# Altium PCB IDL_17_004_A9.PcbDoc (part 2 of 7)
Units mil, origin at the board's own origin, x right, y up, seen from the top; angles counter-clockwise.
Board outline 9493.25 x 7199.68 mil, 6 copper layers (Top Layer - SIG1, Layer 2 - GND1, Layer 3 - PWR1, Layer 4 - PWR2, Layer 5 - GND2, Bottom Layer - SIG2), stack 60.592 mil thick; 403 components, 274 nets, 1834 pads, 1849 vias.
Unrouted connection lines stored in the file: 1.
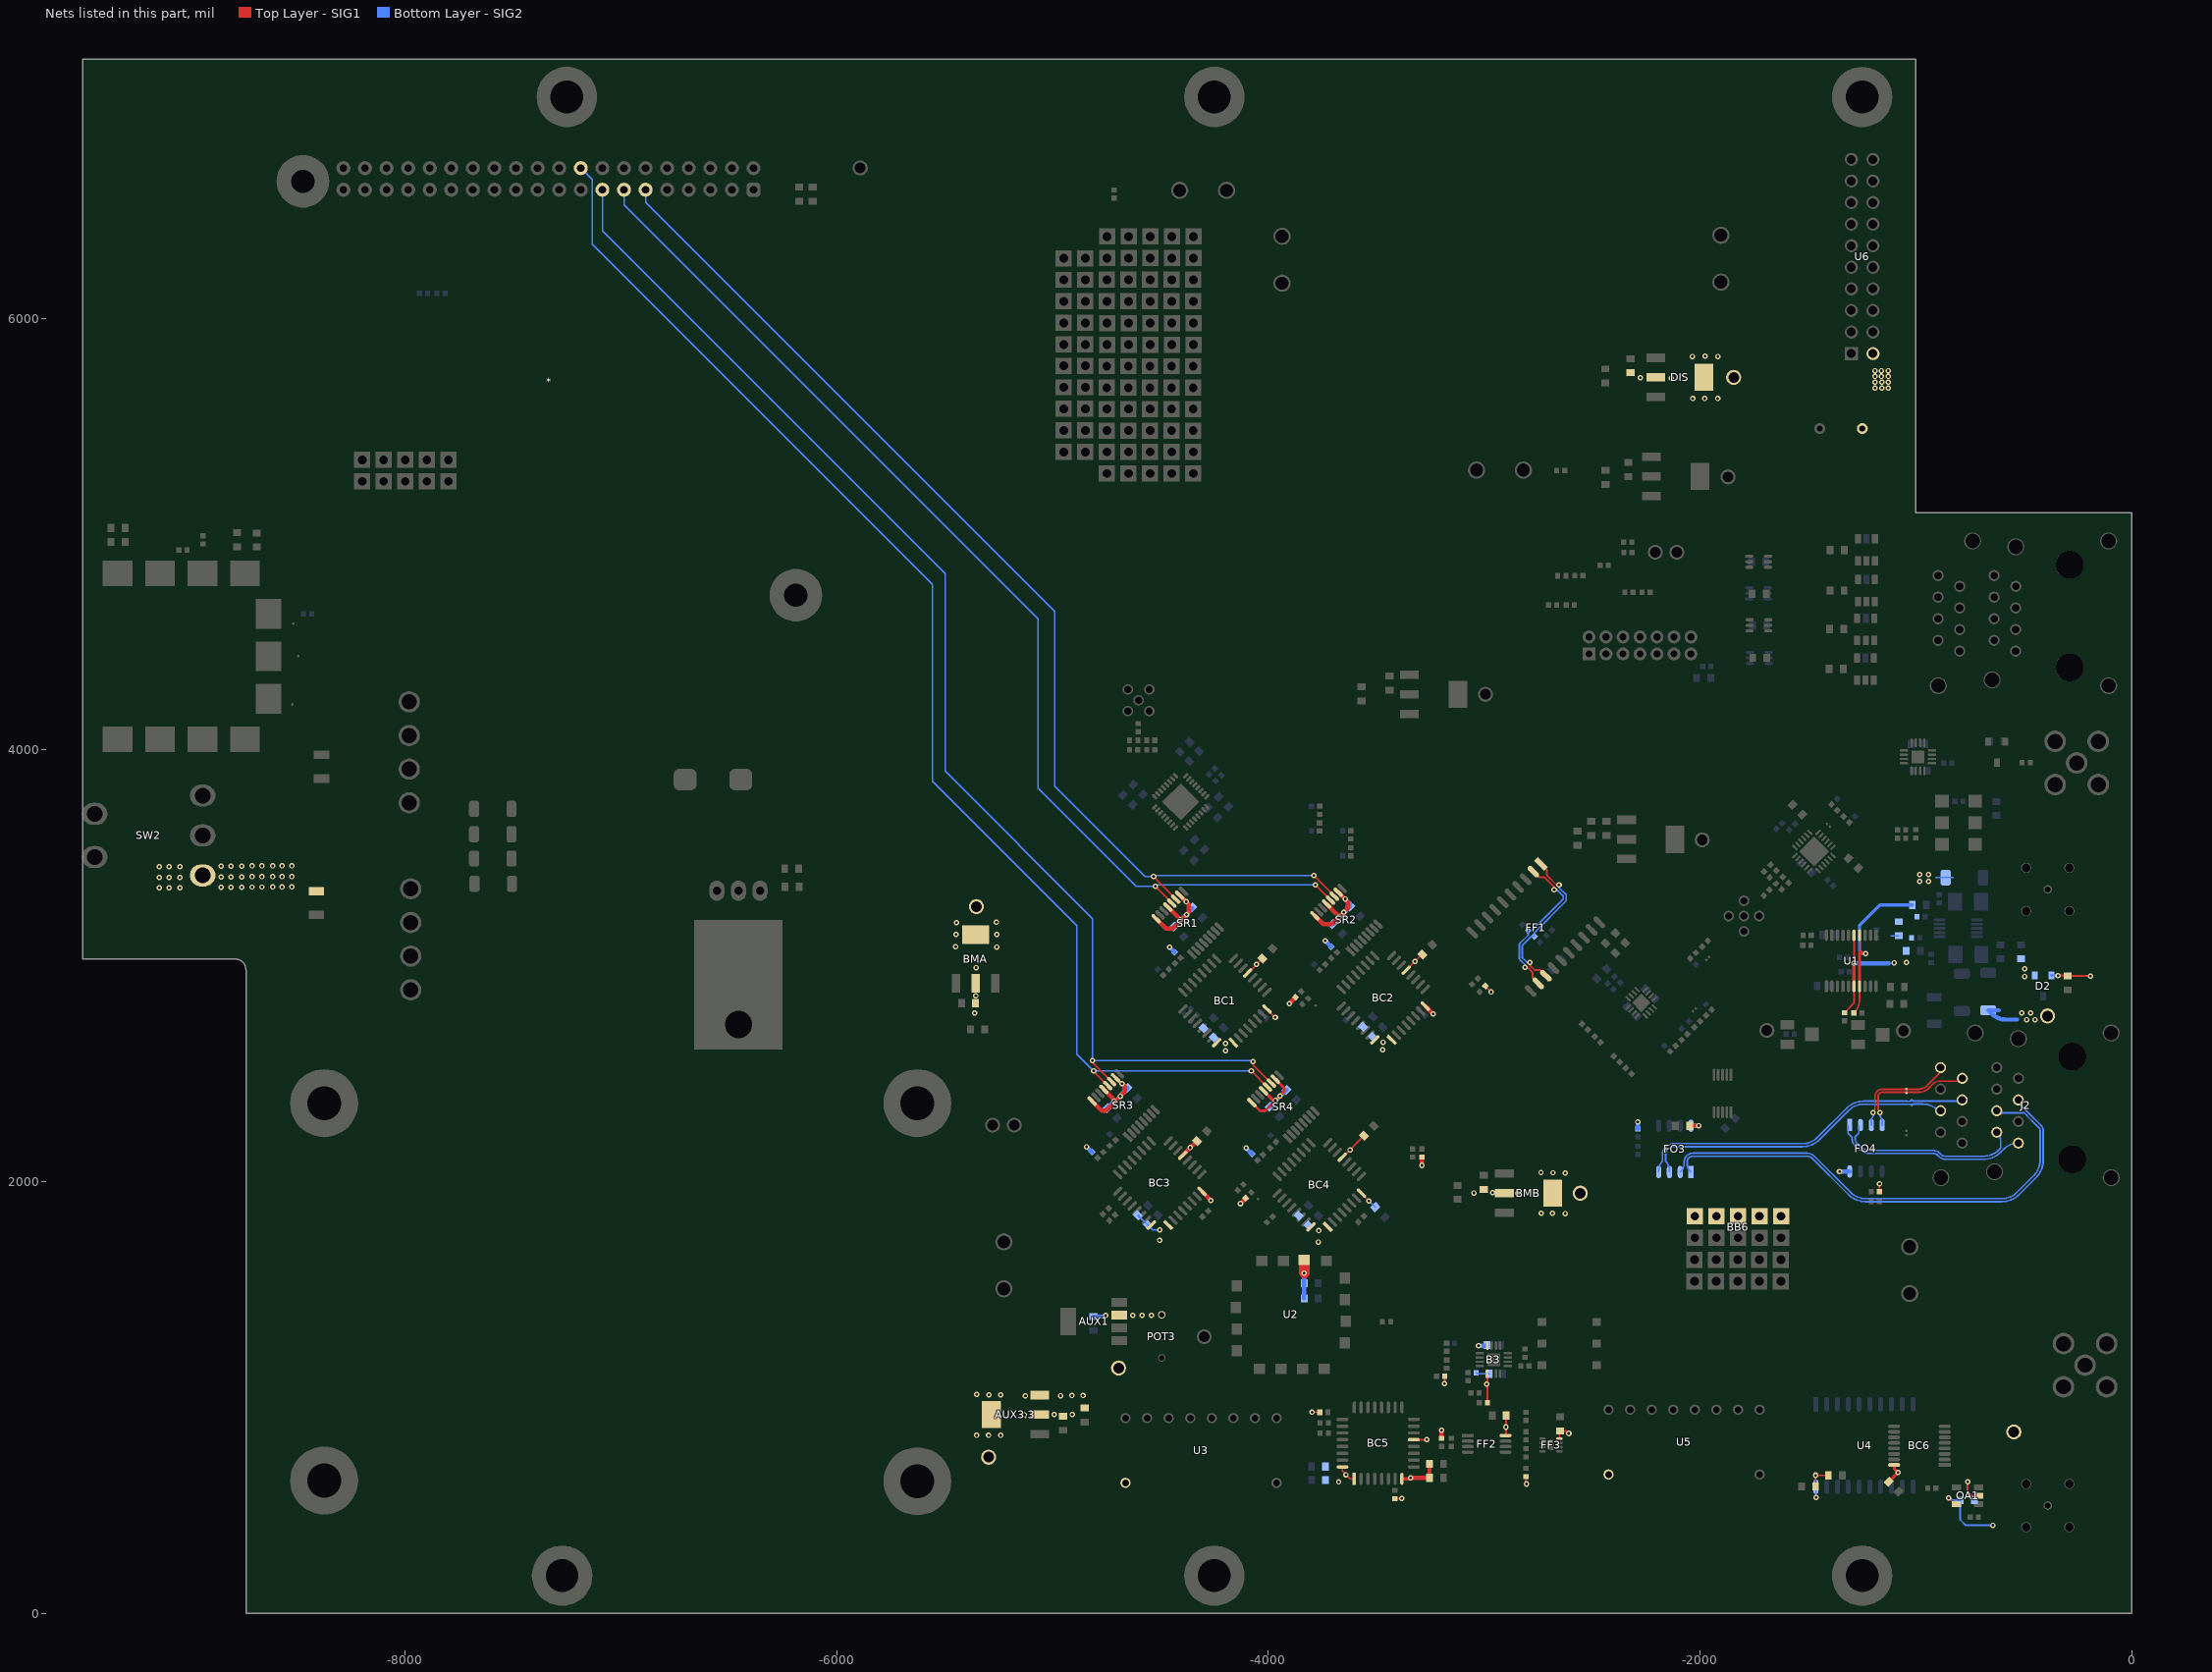
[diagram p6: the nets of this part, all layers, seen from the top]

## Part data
3V +5V -5V AUX3.3V RF3V RM3V RPI_5V TP20 TP21 TP24 TP25 TP30: library part TP, "TEST POINT PC MINI .040\"D BLACK"
*: "CONN HEADER FMAL 40PS.1\" DL GOLD"
AUX1: "IC REG LDO 5V 0.5A SOT223-5"
AUX3: "Linear Voltage Regulator IC Positive Fixed 1 Output 5V 5A TO-220-3"
AUX3.3 BMA BMB DIS JTAG RF RM: "IC REG LDO 3.3V 1A SOT223-3"
B1 B3: "IC CLK BUFFER 1:2 7.5GHZ 16LFCSP"
B2: "IC TRANSLATOR DUAL LVDS 10MSOP"
B4 B6 B7 B9 B10 B12: "IC HIGH DIFF LINE DRIVER SOT23-5"
B5 B8 B11: "IC BUFFER DUAL NON-INV SC706"
B13 B14: "IC DIFF LINE RECEIVER SOT-23-5"
BC1 BC2 BC3 BC4 BC5: "IC COUNTER 8BIT SYNC ECL 32LQFP"
BC6: "IC BINARY COUNTER 8BIT 16-TSSOP"
C1 C2 C3 C4 C5 C6 C8 C9 C11 C12 C13 C14 C15 C16 C17 C28 C34 C35 C36 C37 C38 C42 C43 C46 C47 C48 C49 C50 C51 C52 C53 C54 C55 C56 C59 C60 C61 C62 C63 C64 C65 C66 C67 C69 C70 C71 C72 C73 C74 C75 C76 C77 C78 C79 C80 C81 C86 C87 C102 C103 C104 C105 C106 C107 C108 C109 C110 C111 C112 C114 C115 C116 C118 C119 C400 C401 C402 C403: "CAP CER 1UF 25V X7R 0603"
C7 C10 C18 C19 C20 C21 C22 C23 C24 C25 C39 C40 C41 C44 C45 C57 C58 C68 C82 C83 C84 C85: "CAP CER 1000PF 50V X7R 0402"
C26 C27 C30 C31: "CAP CER 10000PF 50V X7R 0603"
C29 C32 C33 C89 C90 C91 C92 C93 C94 C95 C96 C97 C98 C99 C100 C101 C120: "CAP CER 0.1UF 50V X7R 0603"
C88: "CAP ALUM 470UF 20% 50V RADIAL"
C113: library part 1uF, "CAP CER 1UF 25V X7R 0603"
C117: library part CAPT7343_22U_25V, "Capacitor tantal smd 7343-31 25V 0.1Resr"
C121 C123 C124: "CAP CER 22UF 6.3V X5R 0603"
C122: "CAP CER 100PF 50V NP0 0603"
C125: "CAP CER 4.7PF 50V NP0 0603"
D1 D2: library part "HSMS-2822(seires diode)", "Surface Mount RF Schottky Barrier Diodes, Series Config."
D3 D4 D5 D6 D7 D8 D8: library part D-PMEG3050EP(DIODE), "Schottky diode 6A 30V 500ns 0.36Vf"
F0 F1: library part FUSE-8A6V, "Fuse 8A 6V SMDR"
FAN3 FAN4 J9 J10 J11 J18: "CONN HEADER 2POS 4.2MM VERT TIN"
FF1: "IC D-TYPE POS TRG DUAL 20SOIC"
FF2: "IC D-TYPE POS TRG SNGL 8MSOP"
FF3: "IC TRANSLATOR LVPECL-LVTTL 8-MLF"
FO1: "IC CLK BUFFER 1:8 4GHZ 32MLF"
FO2: "IC CLK BUFFER 1:4 3.5GHZ 16MLF"
FO3 FO4: "IC CLK BUFFER 1:2 650MHZ 8SOIC"
FO5: library part "ADP-2-9(PWR DIV)", "PWR SPL CMB / SM / RoHS5"
FP1: "DOUBLE NIM FRONT PANEL"
GPIO0 GPIO1 GPIO2 TP1 TP2 TP4 TP5 TP7 TP8 TP9 TP10 TP11 TP12 TP13 TP14 TP15 TP16 TP17: library part SMD_TP, "SURFACE MOUNT TEST POINT"
J1 J6: "CONN SMA JACK R/A 50 OHM PCB"
J2 J12: "CONN MOD JACK 8P8C R/A SHIELDED"
J3 J4: "CONN MMCX JACK STR 50 OHM PCB"
J5 J7: "CONN JACK R/A 50 OHM PCB"
J13 J14: "TWO PIN JUMPER"
J15 J17: "CONN HEADER 4POS 3.96MM VERT TIN"
L1 L2: "FIXED IND 10UH 520MA 854 MOHM"
M1: "IC BUFF/MUX SCHMITT-TRIG SC70-6"
MH1 MH2 MH3 MH4 MH5 MH6: "6-32 MOUNTING HOLE"
OA1: "IC OPAMP CFA 400MHZ TSOT23-5"
OSC1: "OSC VCO 127.21MHZ"
PLL1: "IC CLK GEN I2C BUS PROG 24QFN"
POT1: "TRIMMER 10K OHM 0.125W SMD"
POT2: "TRIMMER 2K OHM 0.125W SMD"
POT3: "TRIMMER 10K OHM 0.5W PC PIN"
PWR1: "IC REG BST SEPIC INV ADJ 10MSOP"
R1 R17 R107 R108 R110 R111 R112 R117 R120 R122 R123: "RES SMD 10K OHM 5% 1/16W 0402"
R2: "RES SMD 100 OHM 5% 1/16W 0402"
R3 R4 R5 R8 R18 R19 R20 R21 R23 R24 R27 R28 R29 R34 R35 R36 R40 R41 R42 R43 R44 R45 R46 R55 R56 R57 R58 R59 R60 R61 R62 R63 R64 R68 R72 R73 R74 R75 R76 R77 R78 R79 R80 R81 R85 R91 R94 R95 R96 R97 R99 R100 R102 R103 R104 RA1 RA2 RA3: "RES SMD 49.9 OHM 1% 1/16W 0402"
R6 R7 R38 R125: "RES SMD 1.62K OHM 1% 1/16W 0402"
R9 R10 R13 R14 R26 R31 R47 R48 R49 R50 R65 R66 R82 R83 R89 R90 R98: "RES SMD 127 OHM 1% 1/16W 0402"
R11 R12 R15 R16 R25 R30 R51 R52 R53 R54 R69 R70 R86 R87 R92 R93 R101: "RES SMD 82.5 OHM 1% 1/16W 0402"
R22: "RES SMD 49.9 OHM 1% 1/2W 1206"
R32 R67 R71 R84 R88 R105 R109: "RES SMD 1K OHM 5% 1/16W 0402"
R33 R39 R106: "RES SMD 4.02K OHM 1% 1/16W 0402"
R37: "RES SMD 665 OHM 1% 1/16W 0402"
R113 R114 R115 R116 R118 R119: "RES SMD 10 OHM 5% 1/16W 0402"
R121: "RES SMD 30.1K OHM 1% 1/16W 0402"
R124: "RES SMD 30.9K OHM 1% 1/10W 0402"
RAWPWR1: "AC-DC convertor"
SR1 SR2 SR3 SR4: "IC 8-BIT SHFT REG W/OUT 16-TSSOP"
TP3 TP6: library part "Test point", "TEST POINT PC MINI .040\"D BLACK"
U1: "IC COMPARATOR HS 20-TSSOP"
U2: "OSC VCO 490-540MHZ SMD .5X.5\""
U3 U5: "DIP SW 8POS EXTEND ACTUATOR 24V"
U4: "IC COMPARATOR MAGNITUDE 20SOIC"
U6: "DISPLAY FULL COLOR OLED 1.69\""
U7: "CONN HEADER 14POS 2MM GOLD DIP"

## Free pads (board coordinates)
  round 5 on Top Overlay: 1(-2748.44,6681.85) 1(-2748.44,6681.85) 1(-2748.14,6676.66) 1(-2748.14,6676.66) 1(-2743.81,6672.74) 1(-2743.81,6672.74) 1(-2741.97,6691.61) 1(-2741.97,6691.61) 1(-2739.48,6681.67) 1(-2739.48,6681.67) 1(-2735.29,6695.64) 1(-2735.29,6695.64) 1(-2730.63,6686.62) 1(-2730.63,6686.62) 1(-2729.9,6701.35) 1(-2729.9,6701.35) 1(-2729.9,6701.35) 1(-2729.9,6701.35) 1(-2727.63,6695.24) 1(-2727.63,6695.24) 1(-2695.1,6706.68) 1(-2695.1,6706.68) 1(-2693.19,6700.42) 1(-2693.19,6700.42) 1(-2689.65,6712.89) 1(-2689.65,6712.89) 1(-2687.32,6718.72) 1(-2687.32,6718.71) 1(-2687.32,6718.71) 1(-2687.32,6718.72) 1(-2679.84,6692.48) 1(-2679.84,6692.48) 1(-2676.68,6723.8) 1(-2676.68,6723.8) 1(-2674.12,6687.19) 1(-2674.12,6687.19) 1(-2666.47,6685.46) 1(-2666.47,6685.46) 1(-2666.44,6727.41) 1(-2666.44,6727.41) 1(-2658.56,6726.63) 1(-2658.56,6726.63) 1(-2657.46,6684.14) 1(-2657.46,6684.14) 1(-2649.41,6686.89) 1(-2649.41,6686.89) 1(-2649.08,6726.99) 1(-2649.08,6726.99) 1(-2642.41,6696.28) 1(-2642.41,6696.28) 1(-2641.92,6722.83) 1(-2641.92,6722.83) 1(-2641.66,6705.13) 1(-2641.66,6705.13) 1(-2637.83,6715.63) 1(-2637.83,6715.63) 1(-2518.23,6640.9) 1(-2518.23,6640.9) 1(-2517.85,6645.22) 1(-2517.85,6645.22) 1(-2511.85,6629) 1(-2511.85,6629) 1(-2510.84,6645.5) 1(-2510.84,6645.5) 1(-2504.94,6616.56) 1(-2504.94,6616.56) 1(-2502.47,6646.46) 1(-2502.47,6646.46) 1(-2501.16,6611.22) 1(-2501.16,6611.22) 1(-2496.15,6651.89) 1(-2496.14,6651.89) 1(-2496.14,6651.9) 1(-2496.14,6651.9) 1(-2494.88,6610.18) 1(-2494.88,6610.18) 1(-2489.89,6659.52) 1(-2489.89,6659.52) 1(-2488.9,6618.86) 1(-2488.9,6618.86) 1(-2486.92,6611.01) 1(-2486.92,6611.01) 1(-2486.65,6614.49) 1(-2486.65,6614.49) 1(-2486.34,6620.83) 1(-2486.34,6620.83) 1(-2486.15,6618.5) 1(-2486.15,6618.5) 1(-2485.29,6660.64) 1(-2485.29,6660.64) 1(-2483.78,6614.82) 1(-2483.78,6614.82) 1(-2483.34,6612.32) 1(-2483.34,6612.32) 1(-2483.16,6621.26) 1(-2483.16,6621.26) 1(-2481.75,6657.3) 1(-2481.75,6657.3) 1(-2478.72,6612.49) 1(-2478.72,6612.49) 1(-2473.9,6611.85) 1(-2473.9,6611.85) 1(-2473.34,6642.42) 1(-2473.34,6642.42) 1(-2470.26,6640.19) 1(-2470.26,6640.19) 1(-2470.2,6635.99) 1(-2470.2,6635.99) 1(-2470.04,6631.45) 1(-2470.04,6631.45) 1(-2469.15,6607.36) 1(-2469.15,6607.36) 1(-2466.63,6628.2) 1(-2466.63,6628.2) 1(-2463.6,6625.16) 1(-2463.6,6625.16) 1(-2461.93,6627.19) 1(-2461.93,6627.19) 1(-2460.26,6629.81) 1(-2460.26,6629.81) 1(-2457.92,6605.64) 1(-2457.92,6605.64) 1(-2457.25,6628.54) 1(-2457.25,6628.54) 1(-2455.46,6619.13) 1(-2455.46,6619.13) 1(-2448.15,6610.82) 1(-2448.15,6610.82) 1(-2406.23,6585.93) 1(-2406.23,6585.93) 1(-2405.99,6592.03) 1(-2405.99,6592.03) 1(-2401.49,6599.4) 1(-2401.49,6599.4) 1(-2400.12,6601.97) 1(-2400.12,6601.97) 1(-2398.91,6585.06) 1(-2398.91,6585.06) 1(-2395.52,6600.96) 1(-2395.52,6600.96) 1(-2382.46,6586.78) 1(-2382.46,6586.78) 1(-2378.01,6559.09) 1(-2378.01,6559.09) 1(-2377.62,6563.27) 1(-2377.62,6563.27) 1(-2373.5,6565.41) 1(-2373.5,6565.41) 1(-2372.89,6596.42) 1(-2372.89,6596.42) 1(-2371.26,6551.51) 1(-2371.26,6551.51) 1(-2368.04,6541.09) 1(-2368.04,6541.09) 1(-2367.82,6600.02) 1(-2367.82,6600.02) 1(-2362.77,6595) 1(-2362.77,6595.02) 1(-2362.77,6595.02) 1(-2362.77,6595) 1(-2358.6,6562.29) 1(-2358.6,6562.29) 1(-2357.09,6579.26) 1(-2357.09,6579.26) 1(-2357.03,6542.78) 1(-2357.03,6542.78) 1(-2349.38,6550.55) 1(-2349.38,6550.55) 1(-2343.52,6586.4) 1(-2343.52,6586.4) 1(-2341.89,6594.99) 1(-2341.89,6594.99) 1(-2339.54,6591.49) 1(-2339.54,6591.49) 1(-2336.76,6566.29) 1(-2336.76,6566.29) 1(-2335.73,6514.93) 1(-2335.73,6514.93) 1(-2334.21,6517.42) 1(-2334.21,6517.42) 1(-2333.18,6556.16) 1(-2333.18,6556.16) 1(-2332.75,6511.81) 1(-2332.75,6511.81) 1(-2331.75,6575.29) 1(-2331.75,6575.29) 1(-2331.75,6575.29) 1(-2331.75,6575.29) 1(-2327.55,6521.69) 1(-2327.55,6521.69) 1(-2327.55,6521.69) 1(-2327.55,6521.69) 1(-2325.97,6578.1) 1(-2325.97,6578.1) 1(-2322.16,6548.62) 1(-2322.16,6548.62) 1(-2322.02,6524.42) 1(-2322.02,6524.42) 1(-2320.58,6574.08) 1(-2320.58,6574.08) 1(-2318.77,6522.09) 1(-2318.77,6522.09) 1(-2317.87,6513.47) 1(-2317.87,6513.47) 1(-2315.18,6567.53) 1(-2315.18,6567.53) 1(-2310.18,6561.93) 1(-2310.18,6561.93) 1(-2310.12,6546.47) 1(-2310.12,6546.47) 1(-2308.33,6532.89) 1(-2308.33,6532.89) 1(-2304.08,6522.37) 1(-2304.08,6522.37) 1(-2298.5,6565.86) 1(-2298.5,6565.86) 1(-2287.47,6566.59) 1(-2287.47,6566.59) 1(-2283.09,6526.43) 1(-2283.09,6526.43) 1(-2280.72,6562.91) 1(-2280.72,6562.91) 1(-2273.78,6557.35) 1(-2273.78,6557.35) 1(-2270.28,6528.72) 1(-2270.28,6528.72) 1(-2260.7,6419.82) 1(-2260.7,6419.82) 1(-2259.26,6535.41) 1(-2259.26,6535.41) 1(-2258.16,6410.02) 1(-2258.16,6410.02) 1(-2257.51,6549.79) 1(-2257.51,6549.79) 1(-2256.48,6428.03) 1(-2256.48,6428.03) 1(-2254,6542.26) 1(-2254,6542.26) 1(-2252.07,6400.99) 1(-2252.07,6400.99) 1(-2250.2,6392.64) 1(-2250.2,6392.64) 1(-2248.59,6433.38) 1(-2248.59,6433.38) 1(-2245.82,6386.28) 1(-2245.82,6386.28) 1(-2244.16,6477.46) 1(-2244.16,6477.46) 1(-2243.85,6348.19) 1(-2243.85,6348.19) 1(-2243.19,6374.5) 1(-2243.19,6374.5) 1(-2242.34,6482.93) 1(-2242.34,6482.93) 1(-2242.18,6464.48) 1(-2242.18,6464.48) 1(-2241.58,6362.44) 1(-2241.58,6362.44) 1(-2241.22,6335.29) 1(-2241.22,6335.29) 1(-2239.7,6445.31) 1(-2239.7,6445.31) 1(-2236.14,6484.92) 1(-2236.14,6484.92) 1(-2236.14,6484.92) 1(-2236.13,6484.92) 1(-2235.68,6449.15) 1(-2235.68,6449.15) 1(-2235.58,6454.32) 1(-2235.58,6454.32) 1(-2231.62,6328.06) 1(-2231.62,6328.06) 1(-2219.92,6321.61) 1(-2219.92,6321.61) 1(-2219.08,6473.82) 1(-2219.08,6473.82) 1(-2217.09,6317.62) 1(-2217.09,6317.62) 1(-2214.08,6318.29) 1(-2214.08,6318.29) 1(-2207.3,6324.05) 1(-2207.3,6324.05) 1(-2201.88,6335.86) 1(-2201.88,6335.86) 1(-2196.72,6465.05) 1(-2196.72,6465.05) 1(-2193.76,6344.68) 1(-2193.76,6344.68) 1(-2168.19,6452.2) 1(-2168.19,6452.2) 1(-2167.56,6361.73) 1(-2167.56,6361.73) 1(-2156.67,6443.71) 1(-2156.67,6443.71) 1(-2155.62,6360.97) 1(-2155.62,6360.97) 1(-2147.95,6422.54) 1(-2147.95,6422.54) 1(-2147.91,6432.92) 1(-2147.91,6432.92) 1(-2146.76,6418.81) 1(-2146.76,6418.81) 1(-2145.31,6366.66) 1(-2145.31,6366.66) 1(-2143.87,6419.4) 1(-2143.87,6419.4) 1(-2138.12,6419.5) 1(-2138.12,6419.5) 1(-2135.88,6415.02) 1(-2135.88,6415.02) 1(-2131.64,6405.42) 1(-2131.64,6405.42) 1(-2128.9,6376.03) 1(-2128.9,6376.03) 1(-2121.94,6397.41) 1(-2121.94,6397.41) 1(-2116.64,6394.4) 1(-2116.64,6394.4) 1(-2115.92,6389.71) 1(-2115.92,6389.71)

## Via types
v1: diameter 25, hole 12, Top Layer - SIG1 to Bottom Layer - SIG2, tented both sides, 1502 vias
v2: diameter 25, hole 12, Top Layer - SIG1 to Bottom Layer - SIG2, 184 vias
v3: diameter 25.59, hole 11.81, Top Layer - SIG1 to Bottom Layer - SIG2, tented both sides, 163 vias

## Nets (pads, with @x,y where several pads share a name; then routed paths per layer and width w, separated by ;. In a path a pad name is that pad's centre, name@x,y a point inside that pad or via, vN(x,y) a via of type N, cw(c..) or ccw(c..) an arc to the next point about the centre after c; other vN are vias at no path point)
3V3AUX: AUX3.3.2 AUX3.3.4 AUX3.3V.1 B3.8 B3.13 BC5.1 BC5.8 BC5.13 BC5.32 BC6.16 C70.2 C72.2 C73.2 C74.1 C75.2 C76.1 C77.2 C78.1 C79.2 C80.1 C81.2 C82.2 C85.2 C118.2 FF2.8 FF3.8 R89.2 R90.2 R97.1 R98.2 R99.1 U3.9 U4.20 U5.9 | length 1317.5
  Top Layer - SIG1 w6: v1@-3797.23,931.98 R99.1@-3761.64,931.98 ; C118.2@-1465.12,589.06 v3(-1465.12,640.58)
  Top Layer - SIG1 w8: BC5.32@-3657.1,678.9 -3657.1,659.66 v1(-3640.51,643.08) -3621.22,623.79 BC5.1@-3601.98,623.79 ; R97.1@-3413.1,532.29 v1@-3384.05,532.29 ; v1@-3346.59,623.79 v1(-3341.79,628.59) ; BC5.13@-3326.39,804.89 v3(-3266.82,804.89) ; v3(-3183.9,1065.65) -3182.96,1066.59 C82.2@-3182.96,1099.98 ; B3.13@-2985.65,1110.91 -2985.65,1066.33 v3(-2988.73,1063.25) -2985.15,1059.68 R89.2@-2985.15,976.03 ; FF2.8@-2901.58,824.07 -2898.52,827.13 C81.2@-2898.52,917.38 ; C85.2@-2806.21,634.3 -2806.21,598.98 v3(-2805.21,599.98) ; FF3.8@-2651.84,810.19 -2651.84,843.11 C78.1@-2649.16,845.78 -2620.01,845.78 v3(-2608.21,833.98) ; v3(-1465.12,640.58) ccw(c-1463.87,641.84) -1463.87,640.06 C80.1@-1406.08,640.06
  Top Layer - SIG1 w14: BC5.32@-3669.18,678.9 BC5.32@-3657.1,678.9 ; BC5.8@-3381.51,623.79 v1@-3346.59,623.79 ; C79.2@-1125.97,609.58 -1101.6,633.94 -1101.6,635.4 v1(-1083.84,653.16) -1101.08,670.41 -1101.08,686.67 ccw(c-1102.86,686.67) BC6.16@-1101.6,687.93
  Top Layer - SIG1 w20: v1(-3341.79,628.59) C70.2@-3253.95,628.59 C73.2@-3253.95,693.33 ; v3(-3197.94,848.98) -3197.58,848.61 R98.2@-3197.58,811.96
  Bottom Layer - SIG2 w6: R90.2@-3037.71,1115.58 -3033.04,1110.91 C76.1@-2978.76,1110.91 ; v3(-2988.73,1063.25) v3@-2986.09,1060.62 ; v3(-1465.12,640.58) -1465.12,588.16 U4.20@-1463.79,586.82 v1(-1463.79,537.06)
  Bottom Layer - SIG2 w8: v3(-2988.73,1063.25) -2985.65,1066.33 -2985.65,1104.02 C76.1@-2978.76,1110.91
  Bottom Layer - SIG2 w20: v3@-3198.21,848.98 v3(-3197.94,848.98) ; v3@-3026.03,1240.16 v3(-3026.18,1240.31) -2991.23,1240.31 C75.2@-2987.97,1243.57
  other v1: -3382.94,532.38 -3674.46,609.14 -5351.01,825.24 -5296.01,825.24 -5239.91,825.24 -5130.01,920.24 -4993.01,921.24 -4909.01,921.24 -3797.33,932.07 -5239.91,1012.24 -5295.01,1013.24 -5352.01,1014.24
  other v3: -2900.96,863.73
5VAUX: AUX1.3 AUX3.3.3 C69.1 C71.1 C114.2 C116.2 POT3.1 TP25.1 U2.14 | length 237.1
  Top Layer - SIG1 w50: v1(-3834.29,1577.34) U2.14@-3834.29,1636.2
  Bottom Layer - SIG2 w20: C116.2@-4810.6,1375.54 -4759.12,1375.54 v1(-4753.6,1381.06) ; C69.1@-3834.29,1459.64 C114.2@-3834.29,1530.5 v1(-3834.29,1577.34) cw(c-3832.64,1577.34) v1@-3833.81,1578.5
  other v1: -5125.35,1007.55 -4963.12,1009 -4909.8,1009.52 -4859.11,1009.52 -4627.6,1380.96 -4584.44,1380.96 -4541.29,1380.96
+5V: +5V.1 C30.2 C31.2 C124.1 C125.2 D2.2 D8.1@-862.77,3408.33 OA1.5 R33.2 R124.1 U1.7 U1.14 | length 1479.1
  Top Layer - SIG1 w6: U1.7@-1261.76,2905.63 U1.7@-1261.39,2905.27 ; U1.14@-1261.76,3141.85 -1262,3141.61 -1262,3070.58 -1247.78,3056.37 v1(-1233.25,3056.37)
  Top Layer - SIG1 w8: R33.2@-1287.8,2781 ccw(c-1350.66,2843.87) -1261.76,2843.87 U1.7@-1261.76,2905.63 ; v3(-848.54,535.48) -824.39,511.33 ccw(c-811.68,524.04) OA1.5@-811.68,506.06 ; v3(-342.83,2955.39) -298.94,2955.39 C124.1@-297.22,2953.67 v1@-192.14,2953.67
  Top Layer - SIG1 w15: U1.7@-1261.76,2905.63 -1261.35,2906.04 -1261.35,3021.46 -1261.76,3021.87 -1261.76,3059.56 v1@-1237.13,3059.56
  Bottom Layer - SIG2 w6: -911,3409 -910.33,3408.33 D8.1@-862.77,3408.33 -827.34,3408.33
  Bottom Layer - SIG2 w8: v3(-848.54,535.48) cw(c-846.61,537.42) -849.35,537.42 ccw(c-820.4,566.36) -820.4,525.43 C31.2@-795.46,525.43 -795.46,434.08 -769.96,408.58 v1(-643.71,408.58) ; D2.2@-371.63,2955.46 -342.89,2955.46 v3(-342.83,2955.39)
  Bottom Layer - SIG2 w13: -1262,3187 -1262,3070.58 -1247.78,3056.37 v1(-1233.25,3056.37)
  Bottom Layer - SIG2 w15: -1262,3187 -1166.65,3282.35 C125.2@-1017.3,3282.35 ; D2.2@-371.63,2955.46 cw(c-370.32,2954.15) D2.2@-370.32,2956
  other v1: -192.08,2952.89 -983.62,3391.14 -941.83,3391.14 -983.62,3423.17 -941.83,3423.17
-5V: -5V.1 C30.1 C31.1 C122.2 C123.2 D2.1 D3.2 OA1.2 R39.1 R121.2 U1.6 U1.15 | length 981.3
  Top Layer - SIG1 w6: v3(-760.66,609.6) -760.66,565.28 -740.81,545.43 OA1.2@-709.32,545.43
  Top Layer - SIG1 w8: R39.1@-1332,2782.9 -1287.35,2827.55 U1.6@-1287.35,2905.63
  Top Layer - SIG1 w10: v1(-1287.35,3010.69) U1.15@-1287.35,3141.85
  Top Layer - SIG1 w15: U1.6@-1287.35,2905.63 v1(-1287.35,3010.69)
  Bottom Layer - SIG2 w6: v1(-1287.35,3010.69) cw(c-1292.1,3005.94) v1@-1285.38,3005.94 ; -1118,3139 -1117.37,3139.63 C30.1@-1079.31,3139.63 ; v3(-760.66,609.6) -760.66,555.6 C31.1@-730.5,525.43
  Bottom Layer - SIG2 w20: v1(-1287.35,3010.69) -1126.55,3010.69 -1125.57,3011.68 ; -616.58,2794.16 D3.2@-665.92,2794.16 -652.05,2780.29 ccw(c-581.34,2851) -581.34,2751 -532,2751
  other v1: -488,2751 -448.67,2751 -510,2781 -469.33,2781 -497,2951 -497,2986 -1101.25,3014.83 -1044.25,3015.83
ACDC_PWR: F0.2 SW2.1
  other v1: -9138.37,3361.74 -9092.37,3361.74 -9042.37,3361.86 -8851.29,3364.41 -8805.29,3364.41 -8755.29,3364.53 -8708.42,3365.08 -8662.42,3365.08 -8612.42,3365.2 -8569.42,3365.2 -8523.42,3365.2 -9138.37,3409.62 -9092.37,3409.62 -9042.37,3409.74 -8851.29,3412.29 -8805.29,3412.29 -8755.29,3412.41 -8708.42,3412.96 -8662.42,3412.96 -8612.42,3413.08 -8569.42,3413.08 -8523.42,3413.08 -9138.37,3459.62 -9092.37,3459.62 -9042.37,3459.74 -8851.29,3462.29 -8805.29,3462.29 -8755.29,3462.41 -8708.42,3462.96 -8662.42,3462.96 -8612.42,3463.08 -8569.42,3463.08 -8523.42,3463.08
BMA1_N: FO3.2 J2.4 | length 2293.5
  Bottom Layer - SIG2 w8: FO3.2@-2092.5,2045.14 -2086.72,2050.92 ccw(c-2116.23,2080.42) -2074.5,2080.42 -2074.5,2091.42 cw(c-2033.87,2091.42) -2033.87,2132.06 -1504.76,2132.06 cw(c-1504.76,2084.35) -1471.03,2118.08 -1304.24,1951.29 ccw(c-1233.53,2022) -1233.53,1922 -602.42,1922 ccw(c-602.42,2022) -531.71,1951.29 -454.29,2028.71 ccw(c-525,2099.42) -425,2099.42 -425,2235 ccw(c-449.14,2235) -432.07,2252.07 -499.83,2319 ; J2.4@-626,2329 -616,2319 -499.83,2319 ; -486.01,2306.01 -499.83,2319
BMA1_P: FO3.1 J2.5 | length 2210.2
  Bottom Layer - SIG2 w8: FO3.1@-2042.5,2045.14 -2048.28,2050.92 cw(c-2018.78,2080.42) -2060.5,2080.42 -2060.5,2091.42 cw(c-2033.87,2091.42) -2033.87,2118.06 -1504.76,2118.06 cw(c-1504.76,2084.35) -1480.93,2108.18 -1314.14,1941.39 ccw(c-1233.53,2022) -1233.53,1908 -602.42,1908 ccw(c-602.42,2022) -521.81,1941.39 -444.39,2018.81 ccw(c-525,2099.42) -411,2099.42 -411,2235 ccw(c-449.14,2235) -422.17,2261.97 -476.1,2315.9 -525.67,2365.47 -526.01,2365.47 J2.5@-526.01,2369.01
BMA2_N: FO3.4 J2.12 TP13.1 | length 1578
  Bottom Layer - SIG2 w8: FO3.4@-2192.5,2045.14 -2192.5,2052.23 cw(c-2131.05,2052.23) -2174.5,2095.68 -2174.5,2127.7 cw(c-2129.77,2127.7) -2161.4,2159.32 cw(c-2120.12,2118.04) -2120.12,2176.42 -1527,2176.42 ccw(c-1527,2276.42) -1456.29,2205.71 -1322.27,2339.73 cw(c-1241.66,2259.12) -1241.66,2373.12 -1040.04,2373.12 -1039.93,2373 -1029.66,2373 ccw(c-1029.66,2386.66) TP13.1@-1020,2377 ccw(c-1011.55,2385.45) -1011.55,2373.5 -796.85,2373.5 cw(c-796.85,2358.16) J2.12@-786.01,2369.01
BMA2_P: FO3.3 J2.13 TP12.1 | length 1467
  Bottom Layer - SIG2 w8: FO3.3@-2142.5,2045.14 -2142.5,2052.23 ccw(c-2203.96,2052.23) -2160.5,2095.68 -2160.5,2107.17 -2160.5,2127.7 cw(c-2129.77,2127.7) -2151.5,2149.42 cw(c-2120.12,2118.04) -2120.12,2162.42 -1527,2162.42 ccw(c-1527,2276.42) -1446.39,2195.81 -1312.37,2329.83 cw(c-1241.66,2259.12) -1241.66,2359.12 -1045.84,2359.12 -1045.72,2359 -1027.24,2359 cw(c-1027.24,2348.76) TP12.1@-1020,2356 cw(c-1011.55,2347.55) -1011.55,2359.5 -967.92,2359.5 cw(c-967.92,2259.5) -897.21,2330.21 J2.13@-886,2319
BMA_3V3: BC1.1 BC1.8 BC1.13 BC1.32 BC2.1 BC2.8 BC2.13 BC2.32 BMA.2 BMA.4 C42.1 C43.2 C44.2 C45.2 C46.1 C47.2 C48.1 C49.2 C50.1 C51.2 C52.1 C53.2 C54.1 C109.2 FO3.8 R65.2 R66.2 R67.2 SR1.10 SR1.13 SR1.16 SR2.10 SR2.13 SR2.16 TP20.1 | length 1613.4
  Top Layer - SIG1 w6: BC1.13@-4095.42,2967.07 -4094.96,2967.07 C46.1@-4027.18,3034.84 ; BC1.8@-4006.33,2800.03 -3968.33,2762.03 v3(-3968.08,2762.03) ; -3684.42,3240.45 -3684.42,3239.53 v1(-3672.35,3227.45) ; R66.2@-2994.93,2906.31 v1@-2967.78,2879.17
  Top Layer - SIG1 w8: BC2.32@-3507.64,2656.72 BC2.32@-3507.03,2657.32 ; BC2.13@-3362.27,2980.25 -3320.75,3021.77 -3292.19,3050.33 cw(c-3286.22,3044.36) C51.2@-3286.22,3052.81
  Top Layer - SIG1 w20: SR1.16@-4519.83,3218.43 -4473.99,3172.59 -4444.26,3172.59 v1@-4406.69,3210.16 ; SR1.13@-4465.54,3272.72 v1(-4406.69,3213.86) v1@-4406.69,3210.16 ; SR1.10@-4411.26,3327 -4369.13,3284.87 -4369.13,3247.72 v1(-4379.23,3237.62) v1@-4406.69,3210.16 ; v3(-3903.35,2825.31) R65.2@-3874.36,2854.3 ; SR2.16@-3784.99,3232.45 -3746.05,3193.51 -3706.29,3193.51 v1(-3672.35,3227.45) v1(-3651.35,3248.45) -3632.45,3267.35 -3632.45,3297.06 SR2.10@-3676.42,3341.02 ; SR2.13@-3730.7,3286.73 -3684.42,3240.45 ; BC2.8@-3273.18,2813.22 -3237.42,2777.45 v1(-3237.35,2777.45) ; C48.1@-2045.04,2255 -2040.33,2259.71 v1(-2006.36,2259.71)
  Bottom Layer - SIG2 w20: v1@-4457.08,3085.58 C44.2@-4434.05,3062.56 ; C109.2@-4437.96,3181.2 C49.2@-4352.33,3266.83 ; v1(-3736.84,3116.12) -3708.58,3087.86 C45.2@-3708.58,3087.81 cw(c-3708.58,3092.44) C45.2@-3711.86,3089.17 ; C42.1@-3703.42,3193.51 -3672.35,3224.58 v1(-3672.35,3227.45) v1(-3651.35,3248.45) -3648.48,3248.45 C43.2@-3622.01,3274.92 -3622.01,3288.12 v1(-3644.35,3310.45) ; v1@-3238.35,2777.45 v1(-3237.35,2777.45) ; R67.2@-2288.99,2245.52 v1@-2288.99,2275.73 ; FO3.8@-2042.84,2260.05 FO3.8@-2042.5,2259.71 v1(-2006.36,2259.71)
  other v1: -2289.52,2276.25 -4198.87,2607.5 -3470.42,2610.74 -4198.9,2640.96 -3469.2,2646.2 -5359.95,2782.1 -5355,2862 -2967.78,2878.67 -5353.59,2992.11 -4055.02,3007 -3321.25,3020.77 -4457.08,3086.03 -5448.34,3088.27 -5258.13,3087.57 -5258.83,3144.84 -5447.63,3145.55 -5444.8,3200.7 -5259.54,3202.12 -4380.08,3297.03
BMA_RCLK: *.13 SR1.12 SR2.12 | length 5255.9
  Top Layer - SIG1 w6: *.13@-6988,6622.08 -6985,6625.08 *.13@-6985.26,6625.34 ; v3(-4524.57,3367.93) SR1.12@-4447.45,3290.81 ; v3(-3783.3,3375.52) SR2.12@-3712.61,3304.83
  Bottom Layer - SIG2 w6: *.13@-6985.12,6595.35 -6985.12,6524.12 -5068,4607 -5068,3824 -4611.93,3367.93 v3(-4524.57,3367.93) -4516.98,3375.52 v3(-3783.3,3375.52)
BMA_SRCLK: *.11 SR1.11 SR2.11 | length 5224.2
  Top Layer - SIG1 w6: *.11@-6885.26,6625.34 -6878,6618.08 *.11@-6884,6612.08 ; v3(-4531.57,3413.52) -4531.57,3411.12 SR1.11@-4429.35,3308.91 ; v3(-3788.57,3417.7) -3731.65,3360.77 cw(c-3732.86,3359.56) -3731.15,3359.56 SR2.11@-3694.51,3322.92
  Bottom Layer - SIG2 w6: *.11@-6885.12,6595.35 -6885.12,6537.12 -4990,4642 -4990,3832 -4571.52,3413.52 v3(-4531.57,3413.52) -4527.4,3417.7 v3(-3788.57,3417.7)
BMB1_N: FO4.2 J2.2 | length 862.3
  Bottom Layer - SIG2 w8: FO4.2@-1264.72,2257.4 -1264.72,2224.86 -1282.72,2206.86 -1282.72,2202 ccw(c-1248.23,2202) -1272.62,2177.62 -1260,2165 ccw(c-1211.72,2213.28) -1211.72,2145 -920.01,2145 cw(c-920.01,2103.35) -890.56,2132.8 -885.84,2128.07 ccw(c-861.32,2152.59) -861.32,2117.92 -688.02,2117.92 ccw(c-688.02,2217.92) -617.31,2147.21 -607.56,2156.96 -607.56,2184.48 ccw(c-670.52,2184.48) J2.2@-626,2229
BMB1_P: FO4.1 J2.1 | length 899.1
  Bottom Layer - SIG2 w8: FO4.1@-1314.72,2257.4 -1314.72,2224.86 -1296.72,2206.86 -1296.72,2202 ccw(c-1248.23,2202) -1282.51,2167.72 -1269.9,2155.1 ccw(c-1211.72,2213.28) -1211.72,2131 -920.01,2131 cw(c-920.01,2103.35) -900.46,2122.9 -895.74,2118.18 ccw(c-861.32,2152.59) -861.32,2103.92 -688.02,2103.92 ccw(c-688.02,2217.92) -607.41,2137.31 -593.79,2150.93 ; -593.79,2150.93 cw(c-526.01,2083.14) J2.1@-526.01,2179.01
BMB2_N: FO4.4 J2.10 TP16.1 | length 556.4
  Top Layer - SIG1 w8: v3(-1166.92,2321) cw(c-1145.69,2342.23) -1175.72,2342.23 -1175.72,2396 cw(c-1157.72,2396) -1157.72,2414 TP16.1@-1044.77,2414 ; TP16.1@-1044.68,2412.2 cw(c-1040.34,2407.85) -1040.34,2414 -991,2414 ccw(c-991,2488.36) -938.42,2435.78 -921.07,2453.13 cw(c-890,2422.06) -890,2466 -792.87,2466 ccw(c-792.87,2476.26) J2.10@-785.61,2469.01
  Bottom Layer - SIG2 w8: v3(-1166.92,2321) -1166.92,2304.15 cw(c-1189.14,2281.93) -1157.72,2281.93 FO4.4@-1157.72,2262.4
BMB2_P: FO4.3 J2.9 TP15.1 | length 497.6
  Top Layer - SIG1 w8: v3(-1198.51,2321) ccw(c-1219.74,2342.23) -1189.72,2342.23 -1189.72,2396 cw(c-1157.72,2396) -1157.72,2428 TP15.1@-1048.77,2428 ; TP15.1@-1045.06,2429.9 ccw(c-1040.46,2434.5) -1040.46,2428 -991,2428 ccw(c-991,2488.36) -948.32,2445.68 -893.78,2500.22 ccw(c-912.56,2519) J2.9@-886,2519
  Bottom Layer - SIG2 w8: FO4.3@-1207.72,2262.4 -1207.72,2281.93 cw(c-1176.29,2281.93) -1198.51,2304.15 v3(-1198.51,2321)
BMB_3V3: BB6.1 BB6.2 BB6.3 BB6.4 BB6.5 BC3.1 BC3.8 BC3.13 BC3.32 BC4.1 BC4.8 BC4.13 BC4.32 BMB.2 BMB.4 C55.1 C56.2 C57.2 C58.2 C59.1 C60.2 C61.1 C62.2 C63.1 C64.2 C65.1 C66.2 C67.1 C110.2 FO4.8 R82.2 R83.1 R84.2 SR3.10 SR3.13 SR3.16 SR4.10 SR4.13 SR4.16 TP21.1 | length 1743.7
  Top Layer - SIG1 w6: BC4.13@-3658.36,2113.87 -3656.13,2113.87 C66.2@-3556.97,2213.03
  Top Layer - SIG1 w8: BC3.32@-4541.99,1799.43 BC3.32@-4536.81,1799.43 ; BC4.8@-3569.28,1946.84 -3569.28,1946.58 v1(-3533.94,1911.23) ; R84.2@-1169.8,1954.43 -1169.8,1990.09 v1(-1168.71,1990.09)
  Top Layer - SIG1 w13: SR3.10@-4708.23,2481.99 -4707.19,2481.99 -4707.19,2479.92 v1@-4681.4,2454.13
  Top Layer - SIG1 w14: SR4.16@-4076.84,2366.7 -4038.27,2328.14 -4015.83,2328.14 -3926.49,2417.48 -3926.49,2433.5 SR4.10@-3968.26,2475.28 ; SR4.13@-4022.55,2420.99 -3980.4,2378.84
  Top Layer - SIG1 w20: SR3.16@-4816.8,2373.42 -4779.52,2336.14 ccw(c-4762.09,2353.57) -4762.09,2328.92 ; SR3.13@-4762.51,2427.7 -4717.6,2382.79 v1@-4717.6,2364.56 ; -4759.56,2327.87 cw(c-4759.56,2331.44) -4762.08,2328.91 ; v1@-4681.4,2454.13 v1(-4678.23,2454.13) -4664.45,2440.35 -4664.45,2417.71 v1@-4717.6,2364.56 ; BC3.13@-4397.22,2122.36 -4331.18,2188.41 C63.1@-4331.18,2188.84 ; BC3.8@-4308.14,1955.33 v1@-4266.82,1914.01 ; v3(-4129.23,1898.59) -4105.91,1921.91 R82.2@-4105.91,1923.91 ; v3(-3288.25,2075.63) R83.1@-3288.25,2114.03 ; v3(-1354.72,2047.4) v3@-1353.72,2047.4 ; -4762.08,2328.92 ccw(c-4762.09,2350.26) -4747,2335.17 v1@-4717.6,2364.56
  Bottom Layer - SIG2 w8: C55.1@-4602.66,1843.44 -4559.18,1799.96 C64.2@-4558.95,1799.96 -4535.71,1776.72 v1(-4502.88,1776.72) ; v1(-3533.94,1911.23) -3505.13,1882.43 C61.1@-3504.62,1882.43
  Bottom Layer - SIG2 w20: v1(-4842.15,2162.02) -4818.2,2138.06 C57.2@-4817.2,2138.06 ; C110.2@-4747.28,2340.11 -4747.28,2341.77 v1(-4715.64,2373.42) -4708.75,2373.42 v1(-4686.11,2396.06) -4686.11,2400.28 C60.2@-4653.28,2433.11 -4657.22,2433.11 v1(-4678.23,2454.13) ; v3(-4102.55,2155.69) C58.2@-4075.92,2129.05 ; C62.2@-3994.87,2346.94 -3994.76,2346.94 C67.1@-3916.05,2425.64 ; v3(-1354.72,2047.4) cw(c-1353.67,2046.36) -1353.67,2047.84 FO4.8@-1307.72,2047.84
  other v1: -3768.13,1720.76 -4504.29,1728.95 -3766.13,1773.46 -2625.14,1852.82 -2736.86,1854.23 -2683.83,1853.52 -4266.82,1913.77 -3047.28,1948.28 -2845.76,1947.57 -2961.72,1948.98 -2624.43,2040.2 -2682.41,2041.62 -2737.57,2043.03 -3622,2148 -4361.55,2157.69 -3967.6,2376.37 -3946.94,2397.04
BMB_RCLK: *.18 SR3.12 SR4.12 | length 6096.3
  Top Layer - SIG1 w6: v3(-4809.25,2513.77) -4809.25,2510.63 SR3.12@-4744.42,2445.8 ; v3(-4079.01,2513.64) SR4.12@-4004.46,2439.09
  Bottom Layer - SIG2 w6: *.18@-7185.12,6695.35 -7133,6643.23 -7133,6343.23 -5557,4767.23 -5557,3856 -4887,3186 -4887,2591.53 v3(-4809.25,2513.77) -4079.14,2513.77 v3(-4079.01,2513.64)
BMB_SRCLK: *.15 SR3.11 SR4.11 | length 6017.8
  Top Layer - SIG1 w6: *.15@-7085.26,6596.76 *.15@-7085.26,6625.34 ; v3(-4815.06,2561.13) -4815.06,2552.62 SR3.11@-4726.32,2463.89 ; v1(-4071.06,2557.13) -4071.06,2541.88 SR4.11@-3986.36,2457.18
  Bottom Layer - SIG2 w6: *.15@-7085.12,6595.35 -7085.12,6403.12 -5498,4816 -5498,3902 -4815.06,3219.06 v3(-4815.06,2561.13) -4075.06,2561.13 v1(-4071.06,2557.13)
DD1_Q0_N: FF1.2 FF1.12 R24.1 | length 735.5
  Top Layer - SIG1 w8: v3(-2811.13,2993.13) -2798.69,2993.13 -2776.62,2971.05 -2776.62,2945.59 FF1.12@-2750.12,2919.1 ; FF1.2@-2772.67,3436.63 -2746.18,3410.14 -2720.73,3410.14 -2674.62,3364.03 -2674.62,3354.45 v3(-2676.05,3353.02)
  Bottom Layer - SIG2 w8: v3(-2811.13,2993.13) -2811.13,3005.56 -2833.41,3027.84 -2837.51,3031.95 -2837.51,3101.54 -2833.41,3105.64 -2796.78,3142.28 R24.1@-2796.78,3164.13 -2780.18,3164.13 -2634.47,3309.83 -2634.47,3323.88 -2663.61,3353.02 v3(-2676.05,3353.02)
DD1_Q0_P: FF1.1 FF1.13 R23.1 | length 734.1
  Top Layer - SIG1 w8: v3(-2788.79,3015.46) -2788.79,3003.02 -2766.72,2980.95 -2741.26,2980.95 FF1.13@-2714.77,2954.46 ; FF1.1@-2737.32,3471.98 -2710.83,3445.49 -2710.83,3420.04 -2664.72,3373.93 -2655.14,3373.93 v3(-2653.71,3375.36)
  Bottom Layer - SIG2 w8: v3(-2788.79,3015.46) -2801.23,3015.46 -2823.51,3037.74 -2823.51,3095.74 -2782.78,3136.47 R23.1@-2768.59,3136.47 -2768.59,3153.07 -2620.47,3301.19 -2620.47,3329.68 -2653.71,3362.92 v3(-2653.71,3375.36)
DIS3V3: 3V.1 C88.1 C111.2 DIS.2 DIS.4 U6.2
  other v1: -2034.8,5628 -1979.8,5628 -1918.8,5628 -1189.43,5676.18 -1158.46,5676.18 -1129.48,5676.18 -1189.43,5703.18 -1158.46,5703.18 -1129.48,5703.18 -2133.8,5723 -2276.8,5725 -1189.43,5730.18 -1160.45,5730.18 -1129.48,5730.18 -1189.43,5757.18 -1160.45,5757.18 -1129.48,5757.18 -2035.8,5823 -1917.8,5823 -1976.8,5824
